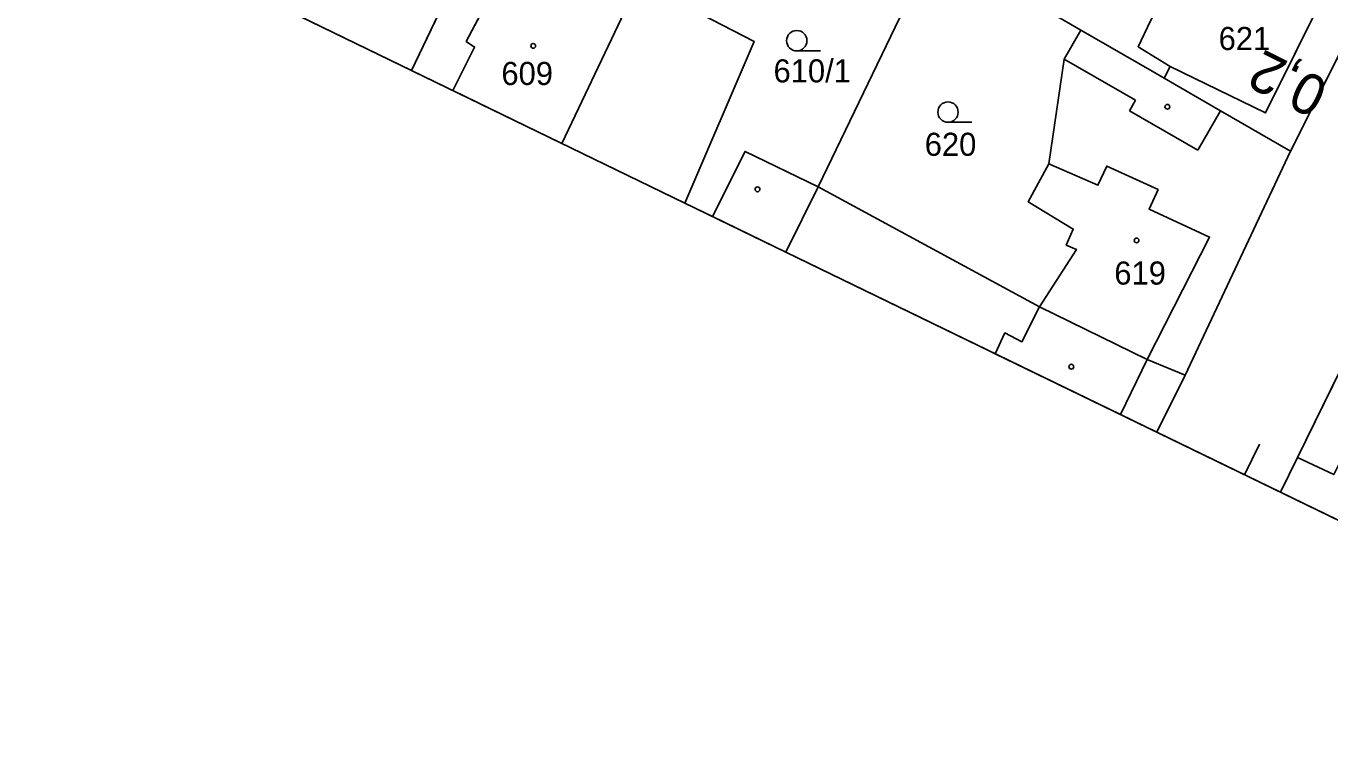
# Model space of a CAD drawing. Extents: x -762314 to -761449, y -993181 to -992589.
# Drawn here: x -762119.9 to -762024, y -992972.2 to -992918.7 of the extents above; entities that cross this region are included whole.
import ezdxf

# ---------------------------------------------------------------- set-up
doc = ezdxf.new("R2010")
doc.units = 0
for name, color, linetype in [('Formáty', 7, 'Continuous'), ('Hranice - vnitř_ kresba', 7, 'Continuous'), ('Hranice parcel', 7, 'Continuous'), ('Obvody jako plochy', 7, 'Continuous'), ('Parcelní čísla', 7, 'Continuous'), ('Vrstva 7', 7, 'Continuous'), ('Značky kultur', 7, 'Continuous'), ('Značky na budově ne v SPI', 7, 'Continuous'), ('Značky na budově v SPI', 7, 'Continuous')]:
    doc.layers.add(name, color=color, linetype=linetype)

msp = doc.modelspace()

# ---------------------------------------------------------------- linework, layer by layer
at = {"layer": 'Formáty'}
msp.add_line((-762030.321, -992951.688), (-762029.23, -992949.439), dxfattribs=at)
msp.add_lwpolyline([(-761558.019, -993180.938), (-762313.703, -992814.139), (-762204.471, -992589.097), (-761448.787, -992955.896)], close=True, dxfattribs=at)
msp.add_lwpolyline([(-761558.019, -993180.938), (-762313.703, -992814.139), (-762204.471, -992589.097), (-761448.787, -992955.896)], close=True, dxfattribs=at)
at = {"layer": 'Hranice - vnitř_ kresba'}
for p, q in [((-762085.305, -992915.566), (-762087.545, -992919.816)), ((-762028.775, -992925.076), (-762024.135, -992915.736)), ((-762080.515, -992927.325), (-762076.135, -992918.116)), ((-762037.235, -992918.316), (-762038.135, -992920.216)), ((-762087.545, -992919.816), (-762086.935, -992920.236)), ((-762086.935, -992920.236), (-762088.54, -992923.43)), ((-762038.135, -992920.216), (-762035.785, -992921.666)), ((-762043.575, -992921.116), (-762038.335, -992924.146)), ((-762035.785, -992921.666), (-762036.235, -992922.516)), ((-762035.785, -992921.666), (-762028.775, -992925.076)), ((-762038.335, -992924.146), (-762038.785, -992924.926)), ((-762038.785, -992924.926), (-762033.765, -992927.826)), ((-762033.765, -992927.826), (-762032.085, -992924.916)), ((-762044.715, -992928.816), (-762041.105, -992930.396)), ((-762041.105, -992930.396), (-762040.445, -992928.986)), ((-762040.445, -992928.986), (-762036.675, -992930.716)), ((-762036.675, -992930.716), (-762037.335, -992932.146)), ((-762037.335, -992932.146), (-762032.885, -992934.216)), ((-762032.885, -992934.216), (-762037.475, -992943.206)), ((-762045.385, -992939.336), (-762046.685, -992941.916)), ((-762047.935, -992941.266), (-762048.658, -992942.788)), ((-762046.685, -992941.916), (-762047.935, -992941.266))]:
    msp.add_line(p, q, dxfattribs=at)
at = {"layer": 'Hranice parcel'}
for p, q in [((-762085.765, -992909.806), (-762091.569, -992921.96)), ((-762085.765, -992909.806), (-762066.375, -992919.826)), ((-762026.935, -992927.896), (-762018.915, -992911.896)), ((-762055.655, -992918.056), (-762061.675, -992930.506)), ((-762045.265, -992917.296), (-762042.345, -992918.986)), ((-762042.345, -992918.986), (-762043.575, -992921.116)), ((-762042.345, -992918.986), (-762037.105, -992922.016)), ((-762066.375, -992919.826), (-762071.476, -992931.713)), ((-762043.575, -992921.116), (-762044.715, -992928.816)), ((-762037.105, -992922.016), (-762036.235, -992922.516)), ((-762036.235, -992922.516), (-762032.085, -992924.916)), ((-762032.085, -992924.916), (-762026.935, -992927.896)), ((-762067.045, -992927.906), (-762069.432, -992932.705)), ((-762061.675, -992930.506), (-762067.045, -992927.906)), ((-762034.675, -992944.376), (-762026.935, -992927.896)), ((-762044.715, -992928.816), (-762046.235, -992931.616)), ((-762064.043, -992935.32), (-762061.675, -992930.506)), ((-762061.675, -992930.506), (-762045.385, -992939.336)), ((-762046.235, -992931.616), (-762042.915, -992933.626)), ((-762042.915, -992933.626), (-762043.425, -992934.796)), ((-762042.685, -992935.116), (-762045.385, -992939.336)), ((-762043.425, -992934.796), (-762042.685, -992935.116)), ((-762020.235, -992937.766), (-762026.415, -992950.416)), ((-762045.385, -992939.336), (-762037.475, -992943.206)), ((-762037.475, -992943.206), (-762039.431, -992947.267)), ((-762037.475, -992943.206), (-762034.675, -992944.376)), ((-762036.775, -992948.556), (-762034.675, -992944.376)), ((-762026.415, -992950.416), (-762027.68, -992952.971)), ((-762023.755, -992951.686), (-762026.415, -992950.416))]:
    msp.add_line(p, q, dxfattribs=at)
at = {"layer": 'Obvody jako plochy'}
for p, q in [((-762085.305, -992915.566), (-762087.545, -992919.816)), ((-762028.775, -992925.076), (-762024.135, -992915.736)), ((-762100.68, -992917.537), (-762091.569, -992921.96)), ((-762080.515, -992927.325), (-762076.135, -992918.116)), ((-762037.235, -992918.316), (-762038.135, -992920.216)), ((-762087.545, -992919.816), (-762086.935, -992920.236)), ((-762086.935, -992920.236), (-762088.54, -992923.43)), ((-762038.135, -992920.216), (-762035.785, -992921.666)), ((-762091.569, -992921.96), (-762071.476, -992931.713)), ((-762035.785, -992921.666), (-762028.775, -992925.076)), ((-762088.54, -992923.43), (-762080.515, -992927.325)), ((-762067.045, -992927.906), (-762069.432, -992932.705)), ((-762061.675, -992930.506), (-762067.045, -992927.906)), ((-762044.715, -992928.816), (-762046.235, -992931.616)), ((-762044.715, -992928.816), (-762041.105, -992930.396)), ((-762041.105, -992930.396), (-762040.445, -992928.986)), ((-762040.445, -992928.986), (-762036.675, -992930.716)), ((-762064.043, -992935.32), (-762061.675, -992930.506)), ((-762036.675, -992930.716), (-762037.335, -992932.146)), ((-762071.476, -992931.713), (-762069.432, -992932.705)), ((-762046.235, -992931.616), (-762042.915, -992933.626)), ((-762037.335, -992932.146), (-762032.885, -992934.216)), ((-762069.432, -992932.705), (-762064.043, -992935.32)), ((-762069.432, -992932.705), (-762064.043, -992935.32)), ((-762042.915, -992933.626), (-762043.425, -992934.796)), ((-762032.885, -992934.216), (-762037.475, -992943.206)), ((-762064.043, -992935.32), (-762039.431, -992947.267)), ((-762042.685, -992935.116), (-762045.385, -992939.336)), ((-762043.425, -992934.796), (-762042.685, -992935.116)), ((-762045.385, -992939.336), (-762046.685, -992941.916)), ((-762045.385, -992939.336), (-762037.475, -992943.206)), ((-762045.385, -992939.336), (-762037.475, -992943.206)), ((-762047.935, -992941.266), (-762048.658, -992942.788)), ((-762046.685, -992941.916), (-762047.935, -992941.266)), ((-762048.658, -992942.788), (-762039.431, -992947.267)), ((-762037.475, -992943.206), (-762039.431, -992947.267)), ((-762039.431, -992947.267), (-762036.775, -992948.556)), ((-762036.775, -992948.556), (-762027.68, -992952.971)), ((-762027.68, -992952.971), (-762000.2, -992966.309))]:
    msp.add_line(p, q, dxfattribs=at)
for points in [[(-762027.68, -992952.971), (-762026.415, -992950.416), (-762020.235, -992937.766), (-762015.665, -992928.496), (-762012.105, -992921.116), (-762003.845, -992904.116), (-761993.715, -992883.396), (-761989.875, -992882.116), (-761991.565, -992881.236), (-762000.575, -992876.526), (-762002.605, -992875.466), (-762001.805, -992877.336), (-762006.215, -992886.076), (-762011.015, -992895.576), (-762017.685, -992909.366), (-762018.915, -992911.896), (-762026.935, -992927.896), (-762034.675, -992944.376), (-762036.775, -992948.556)], [(-762069.432, -992932.705), (-762067.045, -992927.906), (-762061.675, -992930.506), (-762055.655, -992918.056), (-762083.025, -992904.466), (-762085.765, -992909.806), (-762066.375, -992919.826), (-762071.476, -992931.713)], [(-762071.476, -992931.713), (-762066.375, -992919.826), (-762085.765, -992909.806), (-762091.569, -992921.96)], [(-762091.569, -992921.96), (-762085.765, -992909.806)], [(-762080.515, -992927.325), (-762076.135, -992918.116), (-762080.835, -992915.716), (-762081.755, -992917.436), (-762085.305, -992915.566), (-762087.545, -992919.816), (-762086.935, -992920.236), (-762088.54, -992923.43)], [(-762064.043, -992935.32), (-762061.675, -992930.506), (-762067.045, -992927.906), (-762069.432, -992932.705)], [(-762064.043, -992935.32), (-762061.675, -992930.506), (-762067.045, -992927.906), (-762069.432, -992932.705)], [(-762039.431, -992947.267), (-762037.475, -992943.206), (-762045.385, -992939.336), (-762061.675, -992930.506), (-762064.043, -992935.32)], [(-762039.431, -992947.267), (-762037.475, -992943.206), (-762045.385, -992939.336), (-762046.685, -992941.916), (-762047.935, -992941.266), (-762048.658, -992942.788)], [(-762036.775, -992948.556), (-762034.675, -992944.376), (-762037.475, -992943.206), (-762039.431, -992947.267)], [(-762000.2, -992966.309), (-761999.515, -992964.886), (-761998.445, -992962.656), (-761996.515, -992959.536), (-761996.145, -992958.816), (-762007.795, -992952.126), (-762007.185, -992950.676), (-762015.105, -992946.806), (-762020.095, -992944.376), (-762023.755, -992951.686), (-762026.415, -992950.416), (-762027.68, -992952.971)]]:
    msp.add_lwpolyline(points, dxfattribs=at)
for points in [[(-762018.915, -992911.896), (-762030.535, -992906.746), (-762035.755, -992904.206), (-762037.155, -992907.056), (-762043.995, -992915.086), (-762045.265, -992917.296), (-762042.345, -992918.986), (-762037.105, -992922.016), (-762036.235, -992922.516), (-762032.085, -992924.916), (-762026.935, -992927.896)], [(-762037.235, -992918.316), (-762038.135, -992920.216), (-762035.785, -992921.666), (-762028.775, -992925.076), (-762024.135, -992915.736), (-762031.535, -992912.196), (-762033.615, -992916.916), (-762035.935, -992915.696)], [(-762043.425, -992934.796), (-762042.685, -992935.116), (-762045.385, -992939.336), (-762061.675, -992930.506), (-762055.655, -992918.056), (-762053.105, -992912.766), (-762045.265, -992917.296), (-762042.345, -992918.986), (-762043.575, -992921.116), (-762044.715, -992928.816), (-762046.235, -992931.616), (-762042.915, -992933.626)], [(-762037.105, -992922.016), (-762036.235, -992922.516), (-762032.085, -992924.916), (-762026.935, -992927.896), (-762034.675, -992944.376), (-762037.475, -992943.206), (-762045.385, -992939.336), (-762042.685, -992935.116), (-762043.425, -992934.796), (-762042.915, -992933.626), (-762046.235, -992931.616), (-762044.715, -992928.816), (-762043.575, -992921.116), (-762042.345, -992918.986)], [(-762044.715, -992928.816), (-762046.235, -992931.616), (-762042.915, -992933.626), (-762043.425, -992934.796), (-762042.685, -992935.116), (-762045.385, -992939.336), (-762037.475, -992943.206), (-762032.885, -992934.216), (-762037.335, -992932.146), (-762036.675, -992930.716), (-762040.445, -992928.986), (-762041.105, -992930.396)], [(-761992.795, -992951.296), (-762020.235, -992937.766), (-762026.415, -992950.416), (-762023.755, -992951.686), (-762020.095, -992944.376), (-762015.105, -992946.806), (-762007.185, -992950.676), (-762007.795, -992952.126), (-761996.145, -992958.816)]]:
    msp.add_lwpolyline(points, close=True, dxfattribs=at)
at = {"layer": 'Značky kultur'}
for p, q in [((-762061.495, -992920.516), (-762063.245, -992920.516)), ((-762050.375, -992925.766), (-762052.125, -992925.766))]:
    msp.add_line(p, q, dxfattribs=at)
for centre in [(-762063.245, -992919.766), (-762052.125, -992925.016)]:
    msp.add_circle(centre, 0.75, dxfattribs=at)
at = {"layer": 'Značky na budově ne v SPI'}
msp.add_circle((-762035.995, -992924.626), 0.175, dxfattribs=at)
at = {"layer": 'Značky na budově v SPI'}
for centre in [(-762082.625, -992920.146), (-762066.135, -992930.696), (-762038.255, -992934.456), (-762043.055, -992943.746)]:
    msp.add_circle(centre, 0.175, dxfattribs=at)

# ---------------------------------------------------------------- texts
at = {"layer": 'Parcelní čísla'}
for s, p in [('621', (-762032.225, -992920.456)), ('609', (-762084.965, -992923.026)), ('610/1', (-762064.955, -992922.836)), ('620', (-762053.835, -992928.236)), ('619', (-762039.895, -992937.706))]:
    msp.add_text(s, height=1.7, dxfattribs=at).set_placement(p)
at = {"layer": 'Vrstva 7'}
msp.add_text('0,2', height=3, rotation=153.80758, dxfattribs=at).set_placement((-762023.975, -992922.826))

doc.saveas('drawing.dxf')
